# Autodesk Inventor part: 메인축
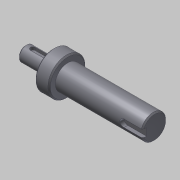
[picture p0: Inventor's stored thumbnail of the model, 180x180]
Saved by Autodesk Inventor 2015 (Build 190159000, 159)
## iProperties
Created: 2018-09
Part Number: 메인축
Document SubType Name: Modeling
Density: 7.86 g/cm^3
Material: 강철, 연강
Appearance: 강철
Mass: 251.954 g
Surface Area: 77.4403 cm^2
Volume: 32.0552 cm^3
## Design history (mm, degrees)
sketch "스케치1"
  geometry: L1 (34.997, -37.5)-(34.997, -77.5) reference; L2 (46.5, -38.401)-(46.5, -76.599) reference; L3 (12.497, -57.5)-(116.5, -57.5); L4 (12.497, -63.5)-(34.997, -63.5); L5 (34.997, -72.5)-(46.5, -72.5); L6 (46.5, -67.5)-(116.5, -67.5); L7 (116.5, -67.5)-(116.5, -57.5); L8 (12.497, -63.5)-(12.497, -57.5); 2 further points
  constraints: 12 end point, 5 point on line, 4 perpendicular, 1 midpoint, 1 parallel
  dimensions: "d0" = 20 diameter of L6 L3; "d1" = 30 diameter of L5 L3; "d2" = 22.5 distance of L4.start L4.end; "d3" = 70 distance of L6.start L6.end; "d5" = 12 diameter of L4 L3
revolve "회전1" sketch "스케치1" stored, may be unused: angle "d4" = 90 deg
chamfer "모따기1" distance "d6" = 1; stored, may be unused: second distance "d7" = 2, angle "d8" = 45 deg
node "작업 평면1"
sketch "스케치2"
  geometry: L1 (-11.25, -5)-(-11.25, 5) reference; L2 (-5.25, 2)-(4.75, 2); L3 (4.75, -2)-(-5.25, -2); A1 r 2 centre (4.75, 0) between (4.75, -2) and (4.75, 2); A2 r 2 centre (-5.25, 0) between (-5.25, 2) and (-5.25, -2); 2 further points
  constraints: 4 end point, 4 point on circle, 4 tangent, 2 centre point, 1 horizontal alignment, 1 midpoint, 1 parallel, 1 perpendicular
  dimensions: "d9" = 4 distance between parallel lines of L3 L2; "d10" = 14 dimension on A1 A2; "d11" = 4 distance edge to line of A2 L1
extrude "돌출1" cut sketch "스케치2" distance "d12" = 2.5; taper "d13" = 0 deg
node "작업 평면2"
sketch "스케치3"
  geometry: L1 (35, 9)-(35, -9) reference; L2 (35, 3)-(20, 3); L3 (20, -3)-(35, -3); A1 r 3 centre (20, 0) between (20, 3) and (20, -3); 2 further points
  constraints: 4 end point, 2 perpendicular, 2 point on circle, 2 point on line, 2 tangent, 1 centre point, 1 horizontal alignment, 1 midpoint
  dimensions: "d14" = 6 distance between parallel lines of L3 L2; "d15" = 18 dimension on A1 L1
extrude "돌출2" cut sketch "스케치3" distance "d16" = 3.5; taper "d17" = 0 deg
node "솔리드1"
node "참조1"
node "참조2"
